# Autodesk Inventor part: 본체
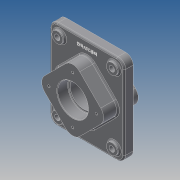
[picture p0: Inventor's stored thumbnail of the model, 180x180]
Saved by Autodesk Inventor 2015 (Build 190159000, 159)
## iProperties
Created: 2026-07
Part Number: 본체
Material: 일반
Document SubType Name: Modeling
Designer: user
Density: 1 g/cm^3
Appearance: 기본값
Mass: 789.782 g
Surface Area: 955.114 cm^2
Volume: 789.782 cm^3
Author: user
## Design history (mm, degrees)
sketch "스케치1"
  geometry: L1 (75, 90)-(-75, 90); L2 (-75, 90)-(-75, -90); L3 (-75, -90)-(75, -90); L4 (75, -90)-(75, 90); L5 (75, 90)-(-75, -90); L6 (-75, 90)-(75, -90); 1 further point
  constraints: 12 end point, 2 midpoint, 2 parallel, 1 horizontal, 1 perpendicular
  dimensions: "d0" = 150 distance of L1.start L1.end; "d1" = 180 distance of L1.end L2.end
extrude "돌출1" new body sketch "스케치1" distance "d2" = 18; taper "d3" = 0 deg
sketch "스케치2"
  geometry: L1 (0, 70.711)-(-70.711, 0); L2 (-70.711, 0)-(0, -70.711); L3 (0, -70.711)-(70.711, 0); L4 (0, 70.711)-(70.711, 0); 1 further point
  constraints: 8 end point, 2 horizontal alignment, 2 vertical alignment, 1 perpendicular
  dimensions: "d4" = 100 distance of L2.end L3.end; "d5" = 100 distance of L1.start L3.end; "d6" = 100 distance of L1.start L1.end
extrude "돌출2" join sketch "스케치2" distance "d7" = 29; taper "d9" = 0 deg; dims "d8" = 41, "d10" = 0
sketch "스케치3"
  geometry: C1 r 11 at (-55, 70); 2 further points
  constraints: 1 centre point, 1 coincident
  dimensions: "d11" = 55 horizontal distance of point (-55, 70) point (0, 0); "d12" = 70 vertical distance of point (0, 0) point (-55, 70); "d13" = 22 diameter of C1
extrude "돌출3" join sketch "스케치3" distance "d14" = 5; taper "d15" = 0 deg
hole "구멍1" diameter "d18" = 11; stored, may be unused: countersink angle "d22" = 82 deg, drill point angle "d24" = 0 deg; dims "d16" = 10, "d17" = 10, "d19" = 6, "d20" = 3.023, "d21" = 2, "d23" = 8
sketch "스케치4"
  geometry: 2 further points
  constraints: 1 coincident
hole "구멍2" sketch "스케치4" at (0, 0) diameter "d31" = 54; stored, may be unused: countersink angle "d35" = 82 deg, drill point angle "d37" = 0 deg; dims "d32" = 6, "d33" = 62, "d34" = 22, "d36" = 8
hole "구멍3" diameter "d40" = 62; stored, may be unused: countersink angle "d44" = 82 deg, drill point angle "d46" = 0 deg; dims "d38" = 10, "d39" = 10, "d41" = 6, "d42" = 62, "d43" = 22, "d45" = 22
sketch "스케치5"
  geometry: 2 further points
  constraints: 1 vertical alignment
  dimensions: "d47" = 48 distance of point (0, 0) point (0, 48)
hole "구멍4" sketch "스케치5" at (0, 48) diameter "d48" = 4.917; stored, may be unused: countersink angle "d52" = 82 deg, drill point angle "d54" = 118 deg; dims "d49" = 10, "d50" = 62, "d51" = 22, "d53" = 13
sketch "스케치6"
  geometry: 2 further points
  constraints: 1 vertical alignment
  dimensions: "d58" = 48 distance of point (0, 0) point (0, -48)
hole "구멍5" sketch "스케치6" at (0, -48) diameter "d59" = 4.917; stored, may be unused: countersink angle "d63" = 82 deg, drill point angle "d65" = 118 deg; dims "d60" = 10, "d61" = 62, "d62" = 22, "d64" = 13
sketch "스케치7"
  geometry: L1 (75, 90)-(-75, 90) reference; 2 further points
  constraints: 1 vertical alignment, 1 other
  dimensions: "d69" = 15 distance from line of point (0, 75) L1
feature "엠보싱1" sketch "스케치7" dims "d0" = 150, "d1" = 180, "d70" = 0.5, "d71" = 0
fillet "모깎기1" dims "d72" = 15
fillet "모깎기2" dims "d73" = 20
fillet "모깎기3" dims "d74" = 20
fillet "모깎기4" dims "d75" = 3
fillet "모깎기5" dims "d76" = 3
fillet "모깎기7" dims "d78" = 3
fillet "모깎기8" dims "d79" = 3
chamfer "모따기1" distance "d80" = 1; stored, may be unused: second distance "d81" = 2, angle "d82" = 45 deg
fillet "모깎기9" dims "d83" = 1
node "솔리드1"
pattern_linear "직사각형 패턴1"
pattern_circular "원형 패턴1" dims angle "d56" = 360 deg
pattern_circular "원형 패턴2" dims angle "d67" = 360 deg
